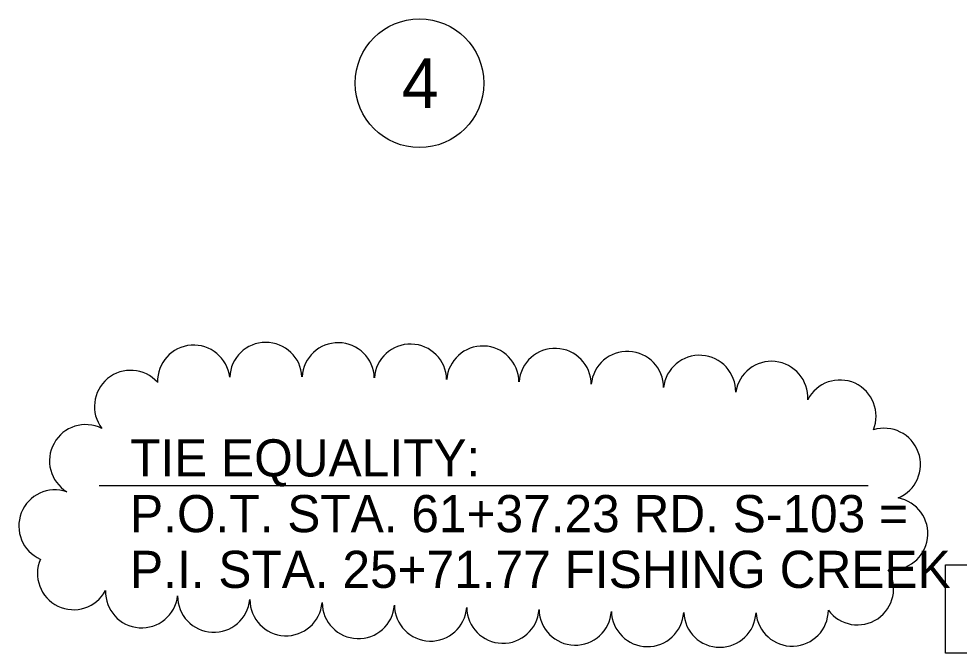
# Model space of a CAD drawing. Extents: x 1964377 to 1966966, y 1116414 to 1123213.
# Drawn here: x 1966498.3 to 1966650.3, y 1118078.4 to 1118180.9 of the extents above; entities that cross this region are included whole.
import ezdxf

# ---------------------------------------------------------------- set-up
doc = ezdxf.new("R2010")
doc.units = 0
for name, color, linetype in [('RD_EX_DV_TX_Prop', 7, 'Continuous'), ('RD_HC_Data', 7, 'Continuous'), ('RD_Sketch1', 7, 'Continuous')]:
    doc.layers.add(name, color=color, linetype=linetype)

msp = doc.modelspace()

# ---------------------------------------------------------------- linework, layer by layer
at = {"layer": 'RD_EX_DV_TX_Prop'}
msp.add_circle((1966563.03, 1118170.47), 10.4, dxfattribs=at)
at = {"layer": 'RD_HC_Data'}
msp.add_line((1966635.58, 1118105.45), (1966511.24, 1118105.45), dxfattribs=at)
for centre, radius, start, end in [((1966526.53, 1118122.32), 5.85, 6.64, 181.64), ((1966538.19, 1118122.76), 5.85, 2.6718, 177.6718), ((1966549.88, 1118122.7), 5.85, 1.6882, 176.6882), ((1966561.57, 1118122.48), 5.85, 1.1689, 176.1689), ((1966573.26, 1118122.17), 5.85, 0.8279, 175.8279), ((1966584.95, 1118121.79), 5.85, 0.442, 175.442), ((1966596.63, 1118121.31), 5.85, 359.8608, 174.8608), ((1966608.3, 1118120.67), 5.85, 358.8796, 173.8796), ((1966619.95, 1118119.7), 5.85, 356.5722, 171.5722), ((1966516.33, 1118118.24), 5.85, 42.0446, 217.0446), ((1966631, 1118116.68), 5.85, 337.8294, 152.8294), ((1966509.06, 1118109.47), 5.85, 63.5572, 238.5572), ((1966638.17, 1118108.89), 5.85, 292.4094, 107.4094), ((1966504.1, 1118098.94), 5.85, 71.0712, 246.0712), ((1966639.36, 1118097.72), 5.85, 264.7476, 79.7476), ((1966507.11, 1118091.28), 5.85, 156.7717, 331.7717), ((1966633.83, 1118088.83), 5.85, 216.5139, 31.5139), ((1966518.12, 1118088.35), 5.85, 178.3924, 353.3924), ((1966529.78, 1118087.63), 5.85, 179.5194, 354.5194), ((1966541.46, 1118087.07), 5.85, 180.0703, 355.0703), ((1966553.15, 1118086.61), 5.85, 180.4138, 355.4138), ((1966564.83, 1118086.21), 5.85, 180.6545, 355.6545), ((1966576.52, 1118085.86), 5.85, 180.8671, 355.8671), ((1966588.21, 1118085.55), 5.85, 181.1504, 356.1504), ((1966623.28, 1118085.4), 5.86, 184.5065, 359.5065), ((1966599.9, 1118085.32), 5.85, 181.5775, 356.5775), ((1966611.59, 1118085.21), 5.85, 182.3387, 357.3387)]:
    msp.add_arc(centre, radius, start, end, dxfattribs=at)
at = {"layer": 'RD_Sketch1'}
msp.add_lwpolyline([(1966648.09, 1118092.67), (1966948.51, 1118092.67), (1966948.51, 1118078.41), (1966648.09, 1118078.41)], close=True, dxfattribs=at)

# ---------------------------------------------------------------- texts
at = {"layer": 'RD_EX_DV_TX_Prop'}
msp.add_text('4', height=8, dxfattribs=at).set_placement((1966560.19, 1118166.48))
at = {"layer": 'RD_HC_Data'}
for s, p in [('TIE EQUALITY:', (1966516.24, 1118106.95)), ('P.O.T. STA. 61+37.23 RD. S-103 =', (1966516.24, 1118097.95)), ('P.I. STA. 25+71.77 FISHING CREEK', (1966516.24, 1118088.95))]:
    msp.add_text(s, height=6, dxfattribs=at).set_placement(p)

doc.saveas('drawing.dxf')
